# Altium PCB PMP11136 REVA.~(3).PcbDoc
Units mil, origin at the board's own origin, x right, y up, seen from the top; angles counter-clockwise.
Board outline 4950 x 3450 mil, 2 copper layers (Top Layer, Bottom Layer), stack 62 mil thick; 162 components, 94 nets, 407 pads, 20 vias.
Unrouted connection lines stored in the file: 297.
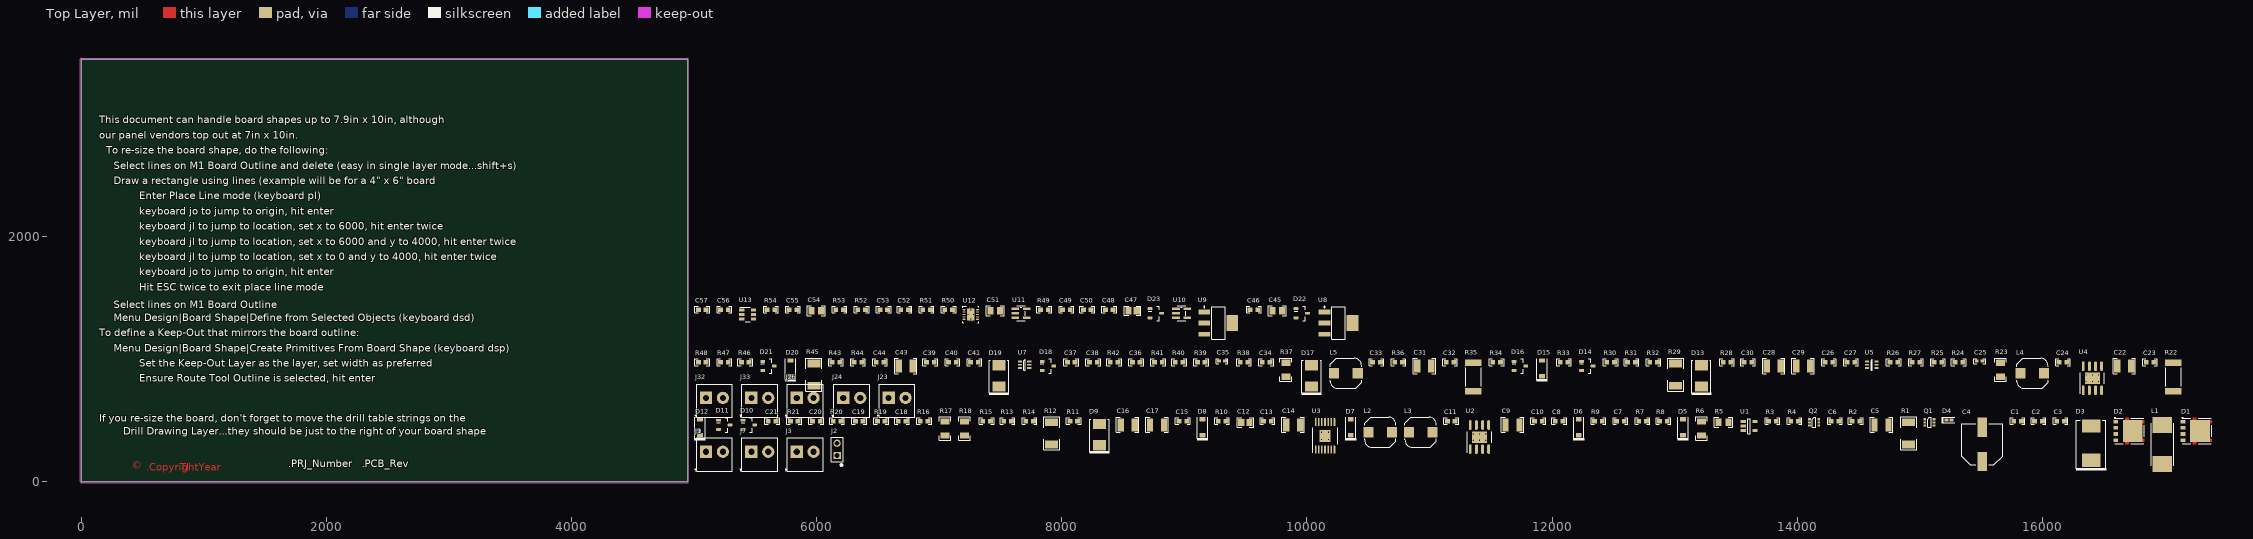
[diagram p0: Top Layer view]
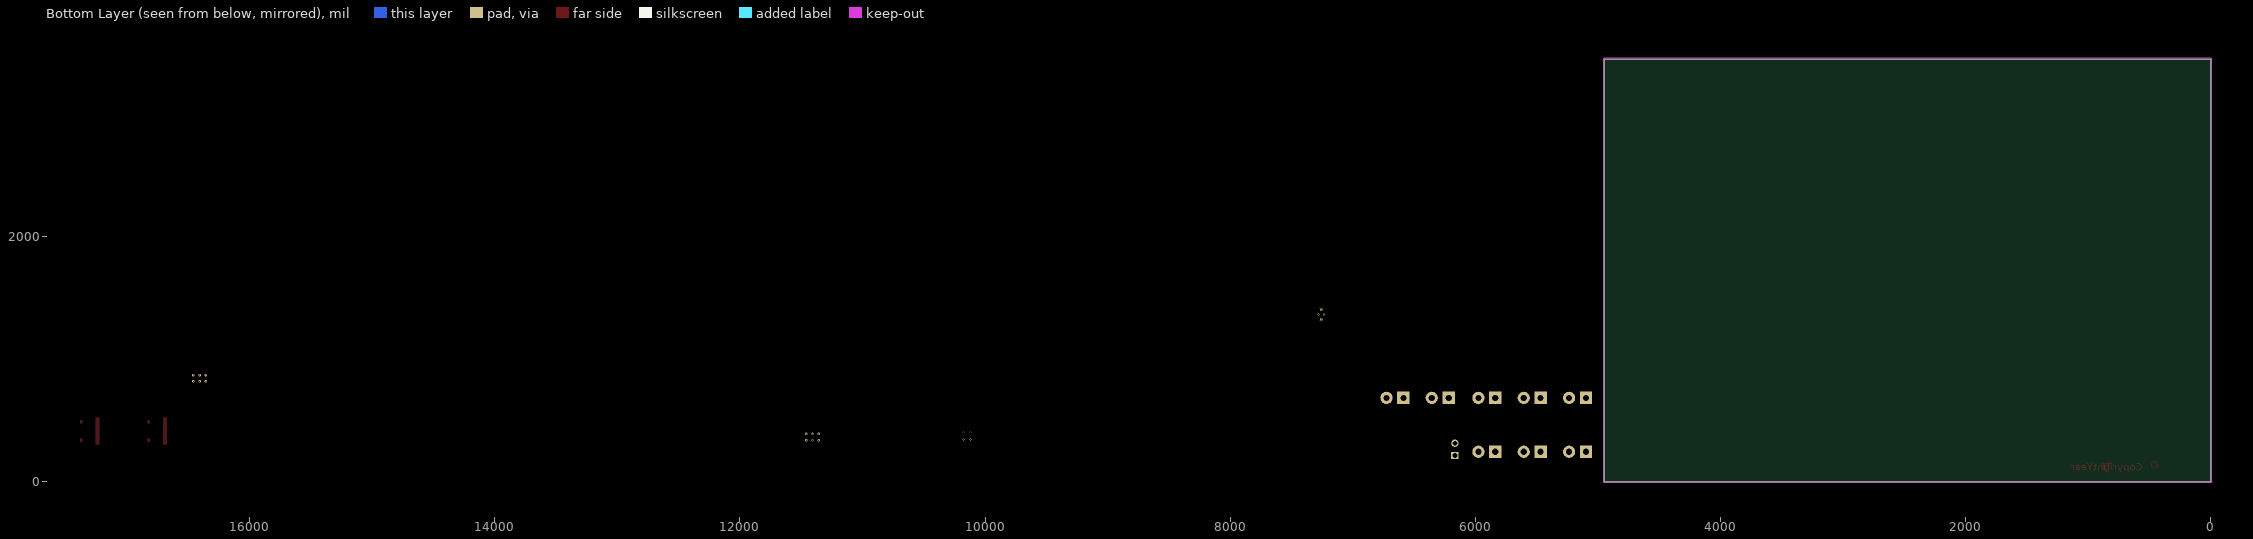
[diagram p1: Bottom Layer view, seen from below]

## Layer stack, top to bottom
Top Solder: solder mask 0.4, Solder Resist, Dk 3.5
Top Layer: signal copper 1.4
Dielectric1: core 59.2, FR-4, Dk 4.8
Bottom Layer: signal copper 1.4
Bottom Solder: solder mask 0.4, Solder Resist, Dk 3.5

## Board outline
0,0 4950,0 4950,3450 0,3450

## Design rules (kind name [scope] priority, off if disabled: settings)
AcuteAngle [All] p1: minimum=4.50000000000000E+0001 checktracksonly=FALSE
AssemblyTestPointUsage [All] p1: valid=2
Clearance Clearance_Keepouts [((IsTrack Or IsArc) And Not InPoly) And IsFree and IsKeepOut vs ((IsTrack Or IsArc) And Not InPoly) And IsFree and IsKeepOut] p1: gap=0
Clearance Clearance_BoardEdge_MountingHoles [OnCopper and InComponentClass('Mounting Holes') vs IsKeepOut] p2: gap=40
Clearance Clearance_BoardEdge_Poly [OnCopper and InPoly vs IsKeepOut] p3: gap=25
Clearance Clearance_BoardEdge [OnCopper and Not InComponentClass('Logo') and not InComponentClass('FiducialMark') and not InRegion(1000,500,4000,800) and Not IsKeepout vs IsKeepOut] p4: gap=75
Clearance Clearance_Poly [InPolygon] p5: gap=25
Clearance [All] p6: gap=7.87
ComponentClearance ComponentClearance_MountingHoles_FiducialMarks [InComponentClass('Mounting Holes') vs InComponentClass('FiducialMark')] p1: gap=50 collisioncheckmode=3 verticalgap=10 showdistances=FALSE
ComponentClearance ComponentClearance_Shunt [InComponentClass('Header') vs InComponentClass('Shunt')] p2: gap=0 collisioncheckmode=3 verticalgap=0 showdistances=FALSE
ComponentClearance ComponentClearance_Logo [InComponentClass('Logo')] p3: gap=50 collisioncheckmode=3 verticalgap=10 showdistances=FALSE
ComponentClearance ComponentClearance_ScrewToNut [(HasFootprint('NY PMS 440 0025 PH')) vs (HasFootprint('Keystone_1902C'))] p4: gap=5 collisioncheckmode=3 verticalgap=10 showdistances=FALSE
ComponentClearance ComponentClearance_MountingHoles [InComponentClass('Mounting Holes')] p5: gap=250 collisioncheckmode=3 verticalgap=100000 showdistances=FALSE
ComponentClearance ComponentClearance_SmallPassives [HasFootprint('0201*') or HasFootprint('0402*') or HasFootprint('0508') or HasFootprint('0603*') or HasFootprint('0612') or HasFootprint('0805*') or HasFootprint('0815*') or HasFootprint('0830*') or HasFootprint('1206*') or HasFootprint('1210*') or HasFootprint('1808*') or HasFootprint('1812*') or HasFootprint('1825*') or HasFootprint('2010*') or HasFootprint('2220*') or HasFootprint('2225*') or HasFootprint('2512*') or HasFootprint('2728*') or HasFootprint('3518*') vs HasFootprint('0201*') or HasFootprint('0402*') or HasFootprint('0508') or HasFootprint('0603*') or HasFootprint('0612') or HasFootprint('0805*') or HasFootprint('0815*') or HasFootprint('0830*') or HasFootprint('1206*') or HasFootprint('1210*') or HasFootprint('1808*') or HasFootprint('1812*') or HasFootprint('1825*') or HasFootprint('2010*') or HasFootprint('2220*') or HasFootprint('2225*') or HasFootprint('2512*') or HasFootprint('2728*') or HasFootprint('3518*')] p6: gap=20 collisioncheckmode=3 verticalgap=10 showdistances=FALSE
ComponentClearance ComponentClearance_THtoSMT [IsThruComponent vs IsSMTComponent] p7: gap=100 collisioncheckmode=3 verticalgap=30 showdistances=FALSE
ComponentClearance ComponentClearance_THtoTH [IsThruComponent vs IsThruComponent] p8: gap=118.11 collisioncheckmode=3 verticalgap=30 showdistances=FALSE
ComponentClearance [All] p9: gap=40 collisioncheckmode=3 verticalgap=10 showdistances=FALSE
DiffPairsRouting [All] p1: maxlimit=100 minlimit=10 mostfreqgap=10 toplayer_minwidth=15 toplayer_maxwidth=15 toplayer_prefwidth=15 bottomlayer_minwidth=15 bottomlayer_maxwidth=15 bottomlayer_prefwidth=15 maxuncoupledlength=1000
FabricationTestPointUsage TestPointUsage [All] p1: valid=2 allowmultiple=FALSE
FabricationTestpoint Testpoint [All] p1: side=3 testpointundercomponent=TRUE minsize=40 maxsize=100 preferedsize=60 minholesize=0 maxholesize=40 preferedholesize=32 testpointgrid=1 allowsidetop=TRUE allowsidebottom=TRUE usegrid=TRUE gridtolerance=0.01
FanoutControl Fanout_LCC [IsLCC] p1: bgadir=Out bgaviamode=Centered fanoutstyle=Auto fanoutdirection=Alternating viagrid=1 // Fanout_LCC (Default Rule)
FanoutControl Fanout_BGA [IsBGA] p2: bgadir=Out bgaviamode=Centered fanoutstyle=Auto fanoutdirection=Alternating viagrid=1 // Fanout_BGA (Default Rule)
FanoutControl Fanout_Default [All] p4: bgadir=Out bgaviamode=Centered fanoutstyle=Auto fanoutdirection=Alternating viagrid=1 // Fanout_Default (Default Rule)
FanoutControl Fanout_Small [(CompPinCount < 5)] p5: bgadir=Out bgaviamode=Centered fanoutstyle=Auto fanoutdirection=OutThenIn viagrid=1 // Fanout_Small (Default Rule)
HoleSize [All] p1: absolutevalues=TRUE maxlimit=251 minlimit=8 maxpercent=80.000 minpercent=20.000
MinimumAnnularRing MinimumAnnularRing_ThermalPadVias [IsVia and InAnyComponent] p1: minimumring=5.91
MinimumAnnularRing [All] p2: minimumring=9
MinimumSolderMaskSliver MinimumSolderMaskSliver_Logo [InComponentClass('Logo') vs InComponentClass('Logo')] p1: minsoldermaskwidth=0.7
MinimumSolderMaskSliver [All] p2: minsoldermaskwidth=3.94
PlaneConnect [All] p1: planeconnectstyle=Relief reliefexpansion=10 reliefentries=4 reliefconductorwidth=10 reliefairgap=10
PolygonConnect [All] p1: connectstyle=Relief reliefconductorwidth=10 reliefentries=4 polygonreliefangle="90 Angle" airgapwidth=10
RoutingVias ThermalPadVias [IsVia and InAnyComponent] p1: holewidth=7.87 width=19.68 viastyle="Through Hole" minholewidth=7.87 minwidth=19.68 maxholewidth=12.99 maxwidth=23.62
RoutingVias [All] p2: holewidth=16 width=34 viastyle="Through Hole" minholewidth=7.87 minwidth=26 maxholewidth=40 maxwidth=65
SilkToBoardRegionClearance [Not ((IsComment or IsDesignator) And (Hide <> 'False')) and not InRegion(1000,500,4000,800)] p1:
SilkToSilkClearance SilkToSilkClearance_Pb-FreeLogo [(HasFootprint('Pb-Free_Overlay_Medium') OR HasFootprint('Pb-Free_Overlay_Small')) vs (HasFootprint('Pb-Free_Overlay_Medium') OR HasFootprint('Pb-Free_Overlay_Small'))] p1: silktosilkclearance=0
SilkToSilkClearance [All] p2: silktosilkclearance=5
SilkToSolderMaskClearance "Silk to Solder Mask Opening" [All] p1: minsilkscreentomaskgap=1 clearancetoexposedcopper=FALSE
SolderMaskExpansion [All] p1: expansion=1.97
UnpouredPolygon [All] p1: allowunpoured=FALSE
Width [All] p1: maxlimit=100 minlimit=6 preferedwidth=10 checkconnectedcopper=TRUE
14 further rules are at their usual default settings.

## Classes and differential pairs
component class "PMP11136 REVA SHEET3": C45 C46 C47 C48 C49 C50 C51 C52 C53 C54 C55 C56 C57 D22 D23 J22 J23 J24 J25 J26 J27 J28 J29 J30 J31 J32 J33 J34 J35 J36 R49 R50 R51 R52 R53 R54 TP30 TP31 TP32 TP33 TP34 TP35 TP36 TP37 TP38 TP39 TP40 U8 U9 U10 U11 U12 U13
component class "PMP11136 REVA SHEET2": C22 C23 C24 C25 C26 C27 C28 C29 C30 C31 C32 C33 C34 C35 C36 C37 C38 C39 C40 C41 C42 C43 C44 D13 D14 D15 D16 D17 D18 D19 D20 D21 J11 J12 J13 J14 J15 J16 J17 J18 J19 J20 J21 L4 L5 R22 R23 R24 R25 R26 R27 R28 R29 R30 R31 R32 R33 R34 R35 R36 R37 R38 R39 R40 R41 R42 R43 R44 R45 R46 R47 R48 TP17 TP18 TP19 TP20 TP21 TP22 TP23 TP24 TP25 TP26 TP27 TP28 TP29 U4 U5 U6 U7
component class "PMP11136 REVA SHEET1": C1 C2 C3 C4 C5 C6 C7 C8 C9 C10 C11 C12 C13 C14 C15 C16 C17 C18 C19 C20 C21 D1 D2 D3 D4 D5 D6 D7 D8 D9 D10 D11 D12 J1 J2 J3 J4 J5 J6 J7 J8 J9 J10 L1 L2 L3 Q1 Q2 R1 R2 R3 R4 R5 R6 R7 R8 R9 R10 R11 R12 R13 R14 R15 R16 R17 R18 R19 R20 R21 TP1 TP2 TP3 TP4 TP5 TP6 TP7 TP8 TP9 TP10 TP11 TP12 TP13 TP14 TP15 TP16 U1 U2 U3
component class Header: J2 J4 J5 J6 J8 J10 J11 J12 J13 J16 J17 J18 J19 J22 J25 J27 J28 J29 J30 J31 J34 J35 J36

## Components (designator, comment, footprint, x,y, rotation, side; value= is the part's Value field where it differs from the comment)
C1 "C1608C0G2A102J" 0603 15798,496 r0 top
C2 "C1608X7R2A103K" 0603 15968,496 r0 top
C3 "C1608X7R1H224K080AB" 0603 16148,496 r0 top
C4 "EEE-FK1H101P" SM_RADIAL_F 15508,306 r90 top
C5 "C3225X7R1H475M250AB" 1210 14688,466 r0 top
C6 "C1608X7R1E105K" 0603 14308,496 r0 top
C7 "C1608X7R1H104K" 0603 12558,496 r0 top
C8 "C1608X7R1H103K" 0603 12058,496 r0 top
C9 "C3225X7R1H475M250AB" 1210 11678,466 r0 top
C10 "C1608X7R1H104K" 0603 11888,496 r0 top
C11 "C1608X7R1H104K" 0603 11178,496 r0 top
C12 "GRM21BR71A106KE51L" 0805 9498,486 r0 top
C13 "C1608X7R1E105K" 0603 9678,496 r0 top
C14 "C3225X7R1C226M250AC" 1210 9888,466 r0 top
C15 "" 0603 8988,496 r0 top
C16 "C3225X7R1C226M250AC" 1210 8538,466 r0 top
C17 "" 1210 8778,466 r0 top
C18 "C1608X7R1H473K" 0603 6698,496 r0 top
C19 "C1608C0G1H151J" 0603 6348,496 r0 top
C20 "" 0603 5998,496 r0 top
C21 "C1608C0G1E682J" 0603 5638,496 r0 top
C22 "C3225X7R1H475M250AB" 1210 16668,946 r0 top
C23 "C1608X7R1H104K" 0603 16878,976 r0 top
C24 "C1608X7R1H104K" 0603 16168,976 r0 top
C25 "C1005X7R1H104K050BB" 0402 15488,986 r0 top
C26 "C1608C0G1H100D" 0603 14258,976 r0 top
C27 "" 0603 14438,976 r0 top
C28 "C3225X7R1C226M250AC" 1210 13808,946 r0 top
C29 "" 1210 14048,946 r0 top
C30 "C1608C0G1H151J" 0603 13598,976 r0 top
C31 "C3225X7R1H475M250AB" 1210 10958,946 r0 top
C32 "C1608X7R1H104K" 0603 11168,976 r0 top
C33 "C1608X7R1H104K" 0603 10568,976 r0 top
C34 "C1608C0G1H151J" 0603 9668,976 r0 top
C35 "C1005X7R1H104K050BB" 0402 9308,986 r0 top
C36 "C1608X7R1H223K" 0603 8608,976 r0 top
C37 "C1608C0G1H152J" 0603 8078,976 r0 top
C38 "" 0603 8258,976 r0 top
C39 "" 0603 6928,976 r0 top
C40 "C1608C0G1H100D" 0603 7108,976 r0 top
C41 "C1608X7R1H104K" 0603 7288,976 r0 top
C43 "C3225X7R1C226M250AC" 1210 6728,946 r0 top
C44 "C1608C0G1H100D" 0603 6518,976 r0 top
C45 "GRM21BR71A106KE51L" 0805_HV 9758,1396 r0 top
C46 "C1608X7R1H104K" 0603 9568,1406 r0 top
C47 "GRM21BR71A106KE51L" 0805 8578,1396 r0 top
C48 "C1608X7R1H104K" 0603 8388,1406 r0 top
C49 "C1608X7R1E105K" 0603 8038,1406 r0 top
C50 "C1608X7R1E105K" 0603 8208,1406 r0 top
C51 "GRM21BR71A106KE51L" 0805_HV 7458,1396 r0 top
C52 "C1608X7R1E105K" 0603 6718,1406 r0 top
C53 "C1608X7R1E105K" 0603 6548,1406 r0 top
C54 "GRM21BR71A106KE51L" 0805_HV 5998,1396 r0 top
C55 "" 0603 5808,1406 r0 top
C56 "C1608X7R1H104K" 0603 5248,1406 r0 top
C57 "C1608C0G2A102J" 0603 5068,1406 r0 top
D1 "MBR1045MFST1G" SO-8FL 17258,416 r0 top
D2 "MBR1045MFST1G" SO-8FL 16708,416 r0 top
D3 "1.5SMC33AT3G" SMC 16398,316 r90 top
D4 "1PS79SB30" SOD-523 15238,506 r0 top
D5 "MMSZ4684T1G" SOD-123 13068,446 r90 top
D6 "MMSZ4705T1G" SOD-123 12218,446 r90 top
D7 "RB070M-30" SOD-123 10358,446 r90 top
D8 "MMSZ4699T1G" SOD-123 9148,446 r90 top
D9 "MBRS360BT3G" SMB 8308,386 r90 top
D10 "BAS16-7-F" SOT-23 5448,466 r0 top
D11 "BAS16-7-F" SOT-23 5248,466 r0 top
D12 "MMSZ5221B-7-F" SOD-123 5048,446 r90 top
D13 "MBRS360BT3G" SMB 13218,866 r90 top
D14 "BAS16-7-F" SOT-23 12288,946 r0 top
D15 "MMSZ5221B-7-F" SOD-123 11918,926 r90 top
D16 "BAS16-7-F" SOT-23 11738,946 r0 top
D17 "MBRS260T3G" SMB 10038,866 r90 top
D18 "BAS16-7-F" SOT-23 7888,946 r0 top
D19 "MBRS260T3G" SMB 7488,866 r90 top
D20 "MMSZ5221B-7-F" SOD-123 5788,926 r90 top
D21 "BAS16-7-F" SOT-23 5608,946 r0 top
D22 "BAS16-7-F" SOT-23 9958,1376 r0 top
D23 "BAS16-7-F" SOT-23 8768,1376 r0 top
J1 "ED555/2DS" TERM_BLK_ED555-2DS 5098,246 r0 top
J2 "PEC02SAAN" CONN_PEC02SAAN 6168,266 r90 top
J3 "ED555/2DS" TERM_BLK_ED555-2DS 5838,246 r0 top
J7 "ED555/2DS" TERM_BLK_ED555-2DS 5468,246 r0 top
J9 "ED555/2DS" TERM_BLK_ED555-2DS 5098,246 r0 top
J23 "ED555/2DS" TERM_BLK_ED555-2DS 6588,686 r0 top
J24 "ED555/2DS" TERM_BLK_ED555-2DS 6218,686 r0 top
J26 "ED555/2DS" TERM_BLK_ED555-2DS 5838,686 r0 top
J32 "ED555/2DS" TERM_BLK_ED555-2DS 5098,686 r0 top
J33 "ED555/2DS" TERM_BLK_ED555-2DS 5468,686 r0 top
L1 "28F0181-1SR-10" 28F0181 16978,306 r90 top
L2 "CLF6045NIT-2R2N-D" CLF6045NI-D 10598,406 r0 top
L3 "CLF6045NIT-4R7N-D" CLF6045NI-D 10928,406 r0 top
L4 "CLF6045NIT-2R2N-D" CLF6045NI-D 15918,886 r0 top
L5 "CLF6045NIT-4R7N-D" CLF6045NI-D 10318,886 r0 top
Q1 "BCR22PN" SOT-363 15078,486 r0 top
Q2 "BC847PN" SOT-363 14138,486 r0 top
R1 "CRCW20107R50JNEF" 2010 14908,396 r90 top
R2 "CRCW060320K0FKEA" 0603 14478,496 r0 top
R3 "CRCW060310K0FKEA" 0603 13798,496 r0 top
R4 "CRCW060310K0FKEA" 0603 13978,496 r0 top
R5 "CRCW080510K0FKEA" 0805_HV 13398,486 r0 top
R6 "CRCW12062K00FKEA" 1206 13218,436 r90 top
R7 "CRCW06032K87FKEA" 0603 12738,496 r0 top
R8 "CRCW06033K01FKEA" 0603 12908,496 r0 top
R9 "CRCW0603100KFKEA" 0603 12378,496 r0 top
R10 "CRCW060334K0FKEA" 0603 9308,496 r0 top
R11 "CRCW0603110RFKEA" 0603 8098,496 r0 top
R12 "" 2010 7918,396 r90 top
R13 "CRCW060310K0FKEA" 0603 7558,496 r0 top
R14 "CRCW060310K0FKEA" 0603 7738,496 r0 top
R15 "" 0603 7388,496 r0 top
R16 "CRCW060353K6FKEA" 0603 6878,496 r0 top
R17 "CRCW120615R0FKEA" 1206 7048,436 r90 top
R18 "CRCW120615R0FKEA" 1206 7208,436 r90 top
R19 "CRCW060310K0FKEA" 0603 6528,496 r0 top
R20 "CRCW06030000Z0EA" 0603 6168,496 r0 top
R21 "CRCW0603200RFKEA" 0603 5818,496 r0 top
R22 "CSRN2512FKR200" 2512 17068,856 r90 top
R23 "CSR1206FK10L0" 1206 15658,916 r90 top
R24 "CRCW06034K02FKEA" 0603 15318,976 r0 top
R25 "CRCW06034K99FKEA" 0603 15148,976 r0 top
R26 "" 0603 14788,976 r0 top
R27 "CRCW060363K4FKEA" 0603 14968,976 r0 top
R28 "CRCW06030000Z0EA" 0603 13428,976 r0 top
R29 "" 2010 13008,876 r90 top
R30 "CRCW0603200RFKEA" 0603 12478,976 r0 top
R31 "CRCW060310K0FKEA" 0603 12648,976 r0 top
R32 "CRCW06034K99FKEA" 0603 12828,976 r0 top
R33 "CRCW0603124KFKEA" 0603 12098,976 r0 top
R34 "CRCW060310K0FKEA" 0603 11548,976 r0 top
R35 "CSRN2512FKR200" 2512 11358,856 r90 top
R36 "CRCW060310K0FKEA" 0603 10748,976 r0 top
R37 "CSR1206FK10L0" 1206 9828,916 r90 top
R38 "CRCW06030000Z0EA" 0603 9488,976 r0 top
R39 "CRCW06034K02FKEA" 0603 9138,976 r0 top
R40 "CRCW060363K4FKEA" 0603 8958,976 r0 top
R41 "CRCW06034K99FKEA" 0603 8788,976 r0 top
R42 "CRCW060354K9FKEA" 0603 8428,976 r0 top
R43 "CRCW0603100KFKEA" 0603 6158,976 r0 top
R44 "CRCW060310K0FKEA" 0603 6338,976 r0 top
R45 "" 2010 5978,876 r90 top
R46 "CRCW06034K99FKEA" 0603 5418,976 r0 top
R47 "CRCW0603200RFKEA" 0603 5248,976 r0 top
R48 "CRCW0603124KFKEA" 0603 5068,976 r0 top
R49 "CRCW060310K0FKEA" 0603 7858,1406 r0 top
R50 "CRCW060310K0FKEA" 0603 7078,1406 r0 top
R51 "CRCW06032K49FKEA" 0603 6898,1406 r0 top
R52 "CRCW06034K99FKEA" 0603 6368,1406 r0 top
R53 "CRCW060310K0FKEA" 0603 6188,1406 r0 top
R54 "CRCW060349K9FKEA" 0603 5628,1406 r0 top
U1 "TPS7B4250QDBV" DBV0005A_N 13608,456 r0 top
U2 "LMR14030PQDDAQ1" DDA0008E_N 11408,366 r90 top
U3 "TPS61175PWP" PWP0014E_N 10148,376 r90 top
U4 "LMR14030PQDDAQ1" DDA0008E_N 16408,846 r90 top
U5 "INA213AQDCKRQ1" DCK0006A_N 14608,956 r0 top
U7 "INA213AQDCKRQ1" DCK0006A_N 7698,956 r0 top
U8 "TPS7B6933QDCYRQ1" DCY0004A_N 10258,1296 r0 top
U9 "TPS7B6950QDCYRQ1" DCY0004A_N 9278,1296 r0 top
U10 "TLV70033QDDCRQ1" DDC0005A_N 8978,1376 r0 top
U11 "TLV70018QDDCRQ1" DDC0005A_N 7668,1376 r0 top
U12 "TPS74701QDRCRQ1" DRC0010A 7258,1366 r0 top
U13 "TPS3808G12QDBVRQ1" DBV0006A_N 5438,1366 r0 top

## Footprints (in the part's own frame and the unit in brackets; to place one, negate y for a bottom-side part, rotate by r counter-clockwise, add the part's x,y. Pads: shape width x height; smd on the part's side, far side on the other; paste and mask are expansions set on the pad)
28F0181 [mm] "SMD, 2-Leads, Body 8.74x4.65mm"
  rect 3.3x4.06 smd: 1(-4.015,0) 2(4.015,0)
  silkscreen extent -4.37,-2.32 4.37,2.32, body extent -4.76,-2.32 4.77,2.32, height 3.05
0402 [mm] "0402 from SM-752 data"
  rect 0.8x0.6 smd: 1(-0.6,0) 2(0.6,0)
  silkscreen extent -1.22,-0.52 1.22,0.52, body extent -0.55,-0.3 0.55,0.3, height 0.6
0603 [mm] "0603 from SM-752 data"
  rect 1x0.95 smd: 1(-0.8,0) 2(0.8,0)
  silkscreen extent -1.52,-0.69 1.52,0.69, body extent -0.87,-0.47 0.87,0.47, height 0.85
0805 [mm] "0805 from SM-752 data"
  rect 1.3x1.5 smd: 1(-0.85,0) 2(0.85,0)
  silkscreen extent -1.72,-0.97 1.72,0.97, body extent -1.1,-0.72 1.1,0.72, height 1.1
0805_HV [mil] "0805 with 30mil clearance between pads"
  rect 50x63 smd: 1(-40,0) 2(40,0)
  silkscreen extent -74,-40 74,40, body extent -43,-29 43,29, height 43
1206 [mm] "1206 from SM-752 data"
  rect 1.3x1.85 smd: 1(-1.45,0) 2(1.45,0)
  silkscreen extent -2.4,-1.21 2.4,1.21, body extent -1.7,-0.9 1.7,0.9, height 1.35
1210 [mm] "1210 from SM-752 data"
  rect 1.3x2.7 smd: 1(-1.45,0) 2(1.45,0)
  silkscreen extent -2.32,-1.57 2.32,1.57, body extent -1.7,-1.35 1.7,1.35, height 1.35
2010 [mm] "Chip Capacitor, Body 5.08x2.54mm, IPC Medium Density"
  rect 1.6x2.7 smd: 1(-2.3,0) 2(2.3,0)
  silkscreen extent -3.42,-1.65 3.42,1.65, body extent -2.73,-1.45 2.73,1.45, height 1.66
2512 [mm] "Chip Resistor, Body 6.3x3.2mm, IPC Medium Density"
  rect 1.3x3.4 smd: 1(-2.95,0) 2(2.95,0)
  silkscreen extent -1.9,-1.6 1.9,1.6, body extent -3.22,-1.67 3.22,1.67, height 0.71
CLF6045NI-D [mm] "SMD, 2-Leads, Body 6.3x6mm, Pitch 4.9mm"
  rect 2.1x2.2 smd: 1(-2.45,0) 2(2.45,0)
  silkscreen extent -3.25,-3.1 3.25,3.1, body extent -3.26,-3.11 3.26,3.11, height 4.8
CONN_PEC02SAAN [mm] "SULLINS"
  rect 1.5x1.5 hole 1.016: 1(-1.27,0)
  round 1.5 hole 1.016: 2(1.27,0)
  silkscreen extent -3.45,-1.27 2.54,1.27, body extent -2.54,-1.27 2.54,1.27, height 8.38
DBV0005A_N [mm] "SOT23, 5-Leads, Body 2.9x1.6mm, Pitch 0.95mm, Lead Span 2.8mm, IPC Medium Density"
  rect 1.1x0.65 smd: 1(-1.2,0.95) 2(-1.2,0) 3(-1.2,-0.95) 4(1.2,-0.95) 5(1.2,0.95)
  silkscreen extent -0.25,-1.55 0.25,1.55, body extent -1.42,-1.46 1.42,1.46, height 1.08
DBV0006A_N [mm] "SOT23, 6-Leads, Body 2.9x1.6mm, Pitch 0.95mm, Lead Span 2.8mm, IPC Medium Density"
  rect 1.1x0.65 smd: 1(-1.2,0.95) 2(-1.2,0) 3(-1.2,-0.95) 4(1.2,-0.95) 5(1.2,0) 6(1.2,0.95)
  silkscreen extent -1.68,-1.55 0.5,1.55, body extent -1.42,-1.46 1.42,1.46, height 1.11
DCK0006A_N [mm] "SOT23, 6-Leads, Body 2x1.3mm, Pitch 0.65mm, Lead Span 2.1mm, IPC Medium Density"
  rect 0.85x0.4 smd: 1(-0.95,0.65) 2(-0.95,0) 3(-0.95,-0.65) 4(0.95,-0.65) 5(0.95,0) 6(0.95,0.65)
  silkscreen extent -0.15,-1.1 0.15,1.1, body extent -1.14,-1 1.14,1, height 0.94
DCY0004A_N [mm] "SOT223/SC73, 4-Leads, Body 6.5x3.5mm, Pitch 2.3mm, Lead Span 7mm, IPC Medium Density"
  rect 2.4x1 smd: 1(-2.9,2.3) 2(-2.9,0) 3(-2.9,-2.3)
  rect 2.4x3.3 smd: 4(2.9,0)
  silkscreen extent -3.02,-3.35 1.4,3.47, body extent -3.5,-3.25 3.5,3.25, height 1.62
DDA0008E_N [mm]
  oval 2x0.6 smd: 1(-2.5,1.905) 2(-2.5,0.635) 3(-2.5,-0.635) 4(-2.5,-1.905) 5(2.5,-1.905) 6(2.5,-0.635) 7(2.5,0.635) 8(2.5,1.905)
  rect 2.4x3.1 smd: 9(0,0)
  silkscreen extent -3.22,-2.5 1.15,2.5, body extent -2.98,-2.45 2.98,2.45, height 1.5
DDC0005A_N [mil]
  rect 62x22 smd: 1(-46,37.4) 2(-46,0) 3(-46,-37.4) 4(46,-37.4) 5(46,37.4)
  silkscreen extent -34,-60 34,60, body extent -60,-60 60,60, height 43
DRC0010A [mm] "SON, 10-Leads, Body 3x3mm, Pitch 0.5mm, Thermal Pad 2.4x1.65mm, TI Recommended"
  oval 0.6x0.24 smd: 1(-1.4,1) 2(-1.4,0.5) 3(-1.4,0) 4(-1.4,-0.5) 5(-1.4,-1) 6(1.4,-1) 7(1.4,-0.5) 8(1.4,0) 9(1.4,0.5) 10(1.4,1)
  rect 1.65x2.4 smd paste-0.825: 11(0,0)
  Top Layer region: 0.135,-1.5 0.365,-1.5 0.365,-1.1 0.135,-1.1
  Top Layer region: -0.135,-1.1 -0.365,-1.1 -0.365,-1.5 -0.135,-1.5
  Top Layer region: -0.135,1.5 -0.365,1.5 -0.365,1.1 -0.135,1.1
  Top Layer region: 0.135,1.1 0.365,1.1 0.365,1.5 0.135,1.5
  silkscreen extent -1.7,-1.7 1.7,1.7, body extent -1.55,-1.55 1.55,1.55, height 1.01
PWP0014E_N [mm] "TSOP, 14-Leads, Body 5x4.4mm, Pitch 0.65mm, Thermal Pad 3x3 mm, IPC Medium Density"
  oval 1.7x0.35 smd: 1(-2.85,1.95) 2(-2.85,1.3) 3(-2.85,0.65) 4(-2.85,0) 5(-2.85,-0.65) 6(-2.85,-1.3) 7(-2.85,-1.95) 8(2.85,-1.95) 9(2.85,-1.3) 10(2.85,-0.65) 11(2.85,0) 12(2.85,0.65) 13(2.85,1.3) 14(2.85,1.95)
  rect 2.46x2.31 smd: 15(0,0)
  silkscreen extent -3.5,-2.65 1.7,2.65, body extent -3.21,-2.5 3.21,2.5, height 0.99
SM_RADIAL_F [mm] "8 x 10.2mm:  Panasonic F"
  rect 4x2 smd: 1(-3.55,0) 2(3.55,0)
  silkscreen extent -4.25,-4.25 4.25,4.25, body extent -4.26,-4.26 4.26,4.26, height 10.5
SMB [mil] "Molded Diode, 2-Leads, Body 5.4x3.6mm, IPC Medium Density, based on OnSemi component dimensions"
  rect 85x107.99 smd: 1(-87.01,0) 2(87.01,0)
  silkscreen extent -155,-82 125,82, body extent -106,-71 106,71, height 91
SMC [mil] "Molded Diode, 2-Leads, Body 6.9x5.8mm, IPC Medium Density, based on OnSemi component dimensions and land patterns"
  rect 110x150 smd: 1(-140.49,0) 2(140.49,0)
  silkscreen extent -221,-124 189,123, body extent -156,-116 156,116, height 91
SO-8FL [mm] "ON SEMICONDUCTOR, DFN5 5x6, 1.27P, CASE 488AA"
  rect 1x0.75 smd: 1(-2.795,1.905) 2(-2.795,0.635) 3(-2.795,-0.635) 4(-2.795,-1.905)
  rect 4.055x4.56 smd: 5(0.698,0)
  Top Layer region: 0,-2.775 0,2.775 -0.905,2.775 -0.905,-2.775
  Top Layer region: 3.2,1.53 3.2,2.28 2.655,2.28 2.655,1.53
  Top Layer region: 3.2,-2.28 3.2,-1.53 2.65,-1.53 2.65,-2.28
  silkscreen extent -3.1,-2.6 3.1,2.9, body extent -3.17,-2.67 3.17,2.67, height 1.11
SOD-123 [mm] "On Semi recommended land pattern"
  rect 0.915x1.22 smd: 1(-1.637,0) 2(1.637,0)
  silkscreen extent -2.74,-1.17 2.03,1.17, body extent -1.93,-0.9 1.93,0.9, height 1.35
SOD-523 [mm] "NXP Semiconductor recommended land pattern, nominal STEP model"
  rect 0.8x0.6 smd paste-0.05: 1(-0.55,0) 2(0.55,0)
  silkscreen extent -1.6,-0.64 1.2,0.64, body extent -0.8,-0.4 0.8,0.4, height 0.72
SOT-23 [mm] "SOT23, 3-Leads, Body 2.9x1.3mm, Pitch 0.95mm, Lead Span 2.5mm, IPC Medium Density"
  rrect50% 1x0.6 smd: 1(-1.2,0.95) 2(-1.2,-0.95) 3(1.2,0)
  silkscreen extent -1.63,-1.5 0.7,1.5, body extent -1.16,-1.45 1.21,1.45, height 1
SOT-363 [mm]
  rect 0.6x0.42 smd mask+0.051: 1(-0.95,0.65) 2(-0.95,0) 3(-0.95,-0.65) 4(0.95,-0.65) 5(0.95,0) 6(0.95,0.65)
  silkscreen extent -0.38,-1.02 0.38,1.02, body extent -1.1,-1.1 1.1,1.1, height 1.12
TERM_BLK_ED555-2DS [mil]
  rect 100x100 hole 50: 1(0,0)
  round 100 hole 50: 2(138,0)
  silkscreen extent -93,-161 215,113, body extent -69,-150 207,106, height 323

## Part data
C1 C57: "CAP, CERM, 1000 pF, 100 V, +/- 5%, C0G/NP0, 0603"
C2: "CAP, CERM, 0.01 µF, 100 V, +/- 10%, X7R, 0603"
C3: "CAP, CERM, 0.22 µF, 50 V, +/- 10%, X7R, 0603"
C4: "CAP, AL, 100 µF, 50 V, +/- 20%, 0.34 ohm, SMD"
C5 C9 C22 C31: library part C3225X7R1E106M, "CAP, CERM, 4.7uF, 50V, +/-20%, X7R, 1210"
C6 C13 C49 C50 C52 C53: library part C1608X7R1C105K, "CAP, CERM, 1uF, 25V, +/-10%, X7R, 0603"
C7 C10 C11 C23 C24 C32 C33 C41 C46 C48 C56: "CAP, CERM, 0.1uF, 50V, +/-10%, X7R, 0603"
C8: "CAP, CERM, 0.01 µF, 50 V, +/- 10%, X7R, 0603"
C12 C47: "CAP, CERM, 10uF, 10V, +/-10%, X7R, 0805"
C14 C16 C28 C43: library part C3225X7R1C226M, "CAP, CERM, 22 µF, 16 V, +/- 20%, X7R, 1210"
C15 C20 C27 C38 C39 C55: library part C1608C0G1H102J, "CAP, CERM, open, 0603"
C17 C29: library part C3225X7R1C226M, "CAP, open, 1210"
C18: "CAP, CERM, 0.047 µF, 50 V, +/- 10%, X7R, 0603"
C19 C30 C34: "CAP, CERM, 150 pF, 50 V, +/- 5%, C0G/NP0, 0603"
C21: "CAP, CERM, 6800 pF, 25 V, +/- 5%, C0G/NP0, 0603"
C25 C35: "CAP, CERM, 0.1uF, 50V, +/-10%, X7R, 0402"
C26 C40 C44: "CAP, CERM, 10 pF, 50 V, +/- 5%, C0G/NP0, 0603"
C36: "CAP, CERM, 0.022 µF, 50 V, +/- 10%, X7R, 0603"
C37: "CAP, CERM, 1500 pF, 50 V, +/- 5%, C0G/NP0, 0603"
C45 C51 C54: "CAP, CERM, 10 µF, 10 V, +/- 10%, X7R, 0805"
D1 D2: "Diode, Schottky, 45 V, 10 A, 6.15x1.00x5.15mm"
D3: library part 1.5SMC6.8A, "Diode, TVS, Uni, 33 V, 1500 W, SMC"
D4: library part 1PS79SB70,115, "Diode, Schottky, 30 V, 0.2 A, SOD-523"
D5: "Diode, Zener, 3.3 V, 500 mW, SOD-123"
D6: "Diode, Zener, 18 V, 500 mW, SOD-123"
D7: library part B130LAW-7-F, "Diode, Schottky, 30V, 1.5A, SOD-123"
D8: "Diode, Zener, 12 V, 500 mW, SOD-123"
D9 D13: library part MBRS260T3G, "Diode, Schottky, 60V, 3A, SMB"
D10 D11 D14 D16 D18 D21 D22 D23: "Diode, Ultrafast, 75V, 0.3A, SOT-23"
D12 D15 D20: "Diode, Zener, 2.4V, 500 mW, SOD-123"
D17 D19: "Diode, Schottky, 60V, 2A, SMB"
J1 J3 J7 J9 J23 J24 J26 J32 J33: "Terminal Block, 6A, 3.5mm Pitch, 2-Pos, TH"
J2: "Header, 100mil, 2x1, Tin, TH"
L1: "Ferrite Bead, 115 ohm @ 100MHz, 10A, SMD, 2-Leads, Body 8.74x4.65mm"
L2 L4: "Inductor, Wirewound, Ferrite, 2.2 µH, 4.1 A, 0.015 ohm, SMD"
L3 L5: "Inductor, Wirewound, Ferrite, 4.7 µH, 3.1 A, 0.023 ohm, SMD"
Q1: library part "BCR 48PN E6327, Infineon Technologies", "Transistor, NPN/PNP Pair, 50 V, 0.1 A, SOT-363"
Q2: library part "BC 846PN H6327, Infineon Technologies", "Transistor, NPN/PNP Pair, 45 V, 0.1 A, SOT-363"
R1: "RES, 7.5, 5%, 0.75 W, 2010"
R2: "RES, 20.0 k, 1%, 0.1 W, 0603"
R3 R4 R13 R14 R19 R31 R34 R36 R44 R49 R50 R53: "RES, 10.0 k, 1%, 0.1 W, 0603"
R5: "RES, 10.0 k, 1%, 0.125 W, 0805"
R6: "RES, 2.00 k, 1%, 0.25 W, 1206"
R7: "RES, 2.87 k, 1%, 0.1 W, 0603"
R8: "RES, 3.01 k, 1%, 0.1 W, 0603"
R9 R43: "RES, 100 k, 1%, 0.1 W, 0603"
R10: "RES, 34.0 k, 1%, 0.1 W, 0603"
R11: "RES, 110, 1%, 0.1 W, 0603"
R12 R29 R45: library part CRCW20102R70JNEF, "RES, open, 2010"
R15 R26: library part CRCW060312K1FKEA, "RES, 12.1 k, 0.1%, 0.1 W, 0603"
R16: "RES, 53.6 k, 1%, 0.1 W, 0603"
R17 R18: "RES, 15.0, 1%, 0.25 W, 1206"
R20 R28 R38: "RES, 0, 5%, 0.1 W, 0603"
R21 R30 R47: "RES, 200, 1%, 0.1 W, 0603"
R22 R35: "RES, 0.2, 1%, 2 W, 2512"
R23 R37: "RES, 0.01, 1%, 0.5 W, 1206"
R24 R39: "RES, 4.02 k, 1%, 0.1 W, 0603"
R25 R32 R41 R46 R52: "RES, 4.99 k, 1%, 0.1 W, 0603"
R27 R40: "RES, 63.4 k, 1%, 0.1 W, 0603"
R33 R48: "RES, 124 k, 1%, 0.1 W, 0603"
R42: "RES, 54.9 k, 1%, 0.1 W, 0603"
R51: "RES, 2.49 k, 1%, 0.1 W, 0603"
R54: "RES, 49.9 k, 1%, 0.1 W, 0603"
U1: "Low Dropout Voltage Tracking LDO, DBV0005A"
U2 U4: library part LMR14030PDDAR, "LMR14030PQDDAQ1, DDA0008E"
U3: "3-A High Voltage Boost Converter with Soft-start and Programmable Switching Frequency, PWP0014E"
U5 U7: library part INA213AIDCK, "Voltage Output, High or Low Side Measurement, Bi-Directional Zero-Drift Series Current-Shunt Monitor, DCK0006A"
U8 U9: "High Voltage Ultra Low Iq - Low Drop Out Regulator, DCY0004A"
U10: "Single Output Automotive LDO, 200 mA, Fixed 3.3 V Output, 2 to 5.5 V Input, with Low IQ, 5-pin SOT (DDC), -40 to 125 degC, Green (RoHS & no Sb/Br)"
U11: "Single Output Automotive LDO, 300 mA, Fixed 1.8 V Output, 2 to 5.5 V Input, with Low IQ, 5-pin SOT (DDC), -40 to 125 degC, Green (RoHS & no Sb/Br)"
U12: "Single Output Automotive LDO, 500 mA, Adjustable 0.8 to 3.6 V Output, 0.8 to 5.5 V Input, with Programmable Soft Start, 10-pin SON (DRC), -40 to 125 degC, Green (RoHS & no Sb/Br)"
U13: library part TPS3808G18QDBVRQ1, "LOW-QUIESCENT-CURRENT PROGRAMMABLE-DELAY SUPERVISORY CIRCUIT, DBV0006A"

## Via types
v1: diameter 19.68, hole 7.87, Top Layer to Bottom Layer, tented top, 12 vias
v2: diameter 19.68, hole 7.87, Top Layer to Bottom Layer, 4 vias
v3: diameter 15.75, hole 7.87, Top Layer to Bottom Layer, 4 vias

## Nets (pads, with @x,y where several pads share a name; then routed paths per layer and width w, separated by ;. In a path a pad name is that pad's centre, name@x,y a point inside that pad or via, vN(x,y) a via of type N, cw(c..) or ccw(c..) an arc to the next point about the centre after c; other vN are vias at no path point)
"3.3V PG": R13.2 U2.6
3.3V_SW: C16.1 C17.1 C56.1 J9.1 L2.2 R4.2 R10.2 R13.1 R34.1 R36.1 R54.2 U13.6
5V#1PG: R34.2 U4.6
GND: C1.2 C2.2 C3.2 C4.2 C5.1 C6.2 C7.2 C8.2 C9.1 C10.2 C12.2 C13.2 C14.2 C16.2 C17.2 C18.2 C20.2 C21.2 C22.1 C23.2 C25.2 C28.2 C29.2 C31.1 C32.2 C35.2 C36.2 C39.2 C41.2 C43.2 C44.2 C45.2 C46.2 C47.2 C48.2 C49.2 C50.2 C51.2 C52.2 C53.2 C54.2 C55.2 C56.2 C57.2 D3.2 D5.2 D9.2 D11.1 D12.2 D13.2 D15.2 D16.1 D19.2 D20.2 D21.1 J1.2 J3.2 J9.2 J23.2 J24.2 J26.2 J32.2 J33.2 Q1.1 Q2.1 R7.2 R8.1 R9.2 R12.1 R14.1 R15.1 R16.1 R17.1 R18.1 R21.1 R29.1 R30.1 R31.1 R32.2 R43.1 R44.1 R45.1 R46.2 R47.1 R52.1 U1.2 U1.5 U2.7 U2.9 U3.7 U3.11 U3.12 U3.13 U3.14 U3.15 U4.7 U4.9 U5.2 U7.2 U8.2 U8.4 U9.2 U9.4 U10.2 U11.2 U12.6 U12.11 U13.2
  other v1: 11356.82,340.41 11408,340.41 11459.18,340.41 11356.82,391.59 11408,391.59 11459.18,391.59 16356.82,820.41 16408,820.41 16459.18,820.41 16356.82,871.59 16408,871.59 16459.18,871.59
  other v2: 7258,1328.6 7235.36,1366 7280.64,1366 7258,1403.4
  other v3: 10118.47,346.47 10177.53,346.47 10118.47,405.53 10177.53,405.53
NetC1_1: C1.1 C2.1 J1.1 L1.1
NetC5_2: C5.2 J2.1 Q2.4 R1.1 R3.2 U1.4
NetC7_1: C7.1 Q2.6 R4.1
NetC8_1: C8.1 D6.1 R6.2 R9.1 U1.1
NetC9_2: C9.2 C10.1 U2.2
NetC11_1: C11.1 U2.1
NetC12_1: C12.1 C13.1 L3.1 U3.3
NetC14_1: C14.1 D7.1 D8.1 J7.1
NetC15_2: C15.2 R12.2
NetC18_1: C18.1 U3.5
NetC19_1: C19.1 D10.1 D11.3 R21.2 U3.6
NetC19_2: C19.2 R20.2
NetC20_1: C20.1 R19.2 U3.8
NetC21_1: C21.1 R19.1
NetC22_2: C22.2 C23.1 U4.2
NetC24_1: C24.1 U4.1
NetC24_2: C24.2 C27.1 D13.1 L4.1 U4.8
NetC25_1: C25.1 C28.1 C29.1 L4.2 R23.1 R25.1 R27.2 U5.3 U5.5
NetC26_1: C26.1 R24.2
NetC26_2: C26.2 C30.1 D14.1 D16.3 R26.1 R30.2
NetC27_2: C27.2 R29.2
NetC30_2: C30.2 R28.2
NetC31_2: C31.2 C32.1
NetC33_1: C33.1
NetC33_2: C33.2 C38.1 D19.1 L5.1
NetC34_1: C34.1 C40.2 D18.1 D21.3 R42.1 R47.2
NetC34_2: C34.2 R38.2
NetC35_1: C35.1 C41.1 D17.1 R37.1 R40.2 R41.1 U7.3 U7.5
NetC36_1: C36.1
NetC37_1: C37.1 C44.1
NetC37_2: C37.2 R43.2
NetC38_2: C38.2 R45.2
NetC39_1: C39.1
NetC40_1: C40.1 R39.2
NetC42_1: C43.1 D17.2 L5.2
NetC45_1: C45.1 J23.1 U8.3
NetC46_1: C46.1 D22.3 U8.1
NetC47_1: C47.1 C49.1 J24.1 U9.3 U10.1
NetC48_1: C48.1 D23.3 U9.1
NetC50_1: C50.1 J26.1 U10.5
NetC51_1: C51.1 R49.2 R50.2 U12.1 U12.2 U12.4
NetC52_1: C52.1 J33.1 U11.5
NetC53_1: C53.1 U11.1
NetC54_1: C54.1 C57.1 J32.1 R51.2 U12.9 U12.10 U13.5
NetC55_1: C55.1 U12.7
NetD1_1: D1.1 D1.2 D1.3 D2.1 D2.2 D2.3 L1.2
NetD4_1: D4.1 J3.1
NetD4_2: D4.2 J2.2 Q2.5 R1.2
NetD5_1: D5.1 R3.1 R7.1
NetD7_2: D7.2 L3.2 U3.1 U3.2
NetD8_2: D8.2 R11.2 U3.9
NetD10_3: D10.3 D12.1
NetD14_3: D14.3 D15.1
NetD18_3: D18.3 D20.1
NetD22_1: D22.1
NetD23_1: D23.1
NetJ5_1: U2.3
NetJ7_2: J7.2 R11.1 R17.2 R18.2
NetJ10_2: U3.4
NetJ12_1: R22.2
NetJ13_1: U4.3
NetJ14_1: R22.1 R23.2 U5.4
NetJ17_1: R36.2
NetJ19_1: R35.2
NetJ20_1: R35.1 R37.2 U7.4
NetJ27_2: U10.3
NetJ30_1: R49.1 U12.3
NetJ31_2: R53.2 U11.3
NetJ34_2: R50.1 U12.5
NetJ35_1: R53.1
NetJ36_1: R54.1 U13.1
NetQ1_2: Q1.2
NetQ1_3: Q1.3 R6.1
NetQ1_5: Q1.5 Q1.6 R2.1
NetQ2_2: Q2.2 R5.1 R8.2
NetQ2_3: Q2.3 R5.2
NetR10_1: R10.1 R14.2 U2.5
NetR15_2: R15.2 U2.4
NetR16_2: R16.2 U3.10
NetR24_1: R24.1 R26.2 U4.4
NetR25_2: R25.2 R32.1 U5.1
NetR27_1: R27.1 R31.2 R33.2 U4.5
NetR33_1: R33.1 U5.6
NetR39_1: R39.1 R42.2
NetR40_1: R40.1 R44.2 R48.2
NetR41_2: R41.2 R46.1 U7.1
NetR48_1: R48.1 U7.6
NetR51_1: R51.1 R52.2 U12.8
SYNC: C11.2 C15.1 D9.1 L2.1 R20.1 R28.1 R38.1 U2.8
VIN_FLTR: C3.1 C4.1 C6.1 D1.5 D2.5 D3.1 Q1.4 R2.2 U1.3
pads on no net: D1.4 D2.4 D6.2 D10.2 D11.2 D14.2 D16.2 D18.2 D21.2 D22.2 D23.2 U10.4 U11.4 U13.3 U13.4

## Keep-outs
Keep-Out Layer:
  lines w10: -5,0 ccw(c0,0) 0,-5 ; -5,0 ccw(c0,0) 0,-5 ; -5,0 -5,3450 ; -5,3450 cw(c0,3450) 0,3455 ; -5,3450 cw(c0,3450) 0,3455 ; 0,-5 4950,-5 ; 0,3455 4950,3455 ; 4950,-5 ccw(c4950,0) 4955,0 ; 4950,-5 ccw(c4950,0) 4955,0 ; 4950,3455 cw(c4950,3450) 4955,3450 ; 4950,3455 cw(c4950,3450) 4955,3450 ; 4955,0 4955,3450
  text ".Layer_Name" at 577,-858.49 h60

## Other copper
Top Layer:
  text ".CopyrightYear" at 532,90 h60
  text "TI" at 808,90 h60
  text "©" at 415,86.48 h105
  text ".Layer_Name" at 577,-858.49 h60
Bottom Layer:
  text ".Layer_Name" at 577,-858.49 h60

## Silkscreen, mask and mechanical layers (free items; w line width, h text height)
Top Overlay:
  text "This document can handle board shapes up to 7.9in x 10in, although" at 150,2925 h60
  text "our panel vendors top out at 7in x 10in." at 150,2800.94 h60
  text "To re-size the board shape, do the following:" at 205,2676.88 h60
  text "Select lines on M1 Board Outline and delete (easy in single layer mode...shift+s)" at 265,2552.82 h60
  text "Draw a rectangle using lines (example will be for a 4\" x 6\" board" at 265,2428.76 h60
  text "Enter Place Line mode (keyboard pl)" at 475,2304.71 h60
  text "keyboard jo to jump to origin, hit enter" at 475,2180.65 h60
  text "keyboard jl to jump to location, set x to 6000, hit enter twice" at 475,2056.59 h60
  text "keyboard jl to jump to location, set x to 6000 and y to 4000, hit enter twice" at 475,1932.53 h60
  text "keyboard jl to jump to location, set x to 0 and y to 4000, hit enter twice" at 475,1808.47 h60
  text "keyboard jo to jump to origin, hit enter" at 475,1684.41 h60
  text "Hit ESC twice to exit place line mode" at 475,1560.35 h60
  text "Select lines on M1 Board Outline" at 265,1416.3 h60
  text "Menu Design|Board Shape|Define from Selected Objects (keyboard dsd)" at 265,1312.24 h60
  text "To define a Keep-Out that mirrors the board outline:" at 150,1188.18 h60
  text "Menu Design|Board Shape|Create Primitives From Board Shape (keyboard dsp)" at 265,1064.12 h60
  text "Set the Keep-Out Layer as the layer, set width as preferred" at 475,940.06 h60
  text "Ensure Route Tool Outline is selected, hit enter" at 475,816 h60
  text "If you re-size the board, don't forget to move the drill table strings on the" at 150,493 h60
  text "Drill Drawing Layer...they should be just to the right of your board shape" at 343,387 h60
  text ".PRJ_Number" at 1690,120 h60
  text ".PCB_Rev" at 2290,120 h60
  text ".Layer_Name" at 577,-858.49 h60
Bottom Overlay:
  text ".Layer_Name" at 577,-858.49 h60
Top Paste:
  text ".Layer_Name" at 577,-858.49 h60
Bottom Paste:
  text ".Layer_Name" at 577,-858.49 h60
Top Solder:
  text ".Layer_Name" at 577,-858.49 h60
  text ".Layer_Name" at 577,-858.49 h60
Bottom Solder:
  text ".Layer_Name" at 577,-858.49 h60
Drill Guide:
  text ".Layer_Name" at 577,-858.49 h60
M1 Board Outline:
  the board outline again, w10
  text ".Layer_Name" at 577,-858.49 h60
M2 Board Dimensions:
  rectangle: 0,-275 125,-150
  rectangle: 125,-400 500,-275
  lines w7: 0,-275 1000,-275 ; 125,-400 125,-150 ; 250,-400 250,-150 ; 500,-400 500,-150 ; 750,-400 750,-150 ; 0,-400 1000,-400 1000,-150 0,-150 0,-400
  text ".Layer_Name" at 577,-858.49 h60
M3 3D STEP Top:
  text ".Layer_Name" at 577,-858.49 h60
M4 3D STEP Bottom:
  text ".Layer_Name" at 577,-858.49 h60
M5 Assembly Top:
  lines w10: -292,-930.17 6308,-930.17 ; -292,-726.83 6310,-726.83 ; -292,-523.5 -292,-1133.5 3713,-1133.5 6310,-1133.5 6310,-523.5 -291.5,-523.5 -291.5,-1133.5 1284,-1133.5 ; 2173,-1133.5 2173,-523.5 ; 3440,-726.83 3440,-523.5 ; 4280,-726.83 4280,-523.5 ; 4902,-1140 4902,-937.17
  text "COMPONENTS MARKED 'DNP' SHOULD NOT BE POPULATED." at 1153.5,-318.5 h60
  text "ASSEMBLY VARIANT:" at 1153,-434 h60
  text ".VariantName" at 2189,-434 h60
  text "PCB VIEWED FROM TOP SIDE" at -228.5,-655.67 h60
  text "BOARD #:" at 2248,-655.67 h60
  text ".PRJ_Number" at 2793.5,-655.67 h60
  text "REV:" at 3638,-655.67 h60
  text ".PCB_Rev" at 3929.5,-655.67 h60
  text "SVN REV:" at 4476,-655.67 h60
  text ".VersionControl_RevNumber" at 4982,-655.67 h60
  text "PLOT NAME =" at -228.5,-1064.34 h60
  text ".plot_File_Name" at 577,-1064.34 h60
  text "GENERATED    :" at 2250,-1064.34 h60
  text ".Print_Date" at 3119.5,-1064.34 h60
  text ".Print_Time" at 3848.5,-1064.34 h60
  text "TEXAS INSTRUMENTS" at 5113,-1064.34 h60
M6 Assembly Bottom:
  lines w10: -292.5,-727.33 6309.5,-727.33 ; -290.5,-930.67 6309.5,-930.67 ; 1115.5,-1140.5 1115.5,-937.67 ; 1737.5,-727.33 1737.5,-524 ; 2577.5,-727.33 2577.5,-524 ; 3844.5,-1134 3844.5,-524 ; 4733.5,-1134 6309,-1134 6309,-524 -292.5,-524 -292.5,-1134 2304.5,-1134 6309.5,-1134 6309.5,-524
  text "COMPONENTS MARKED 'DNP' SHOULD NOT BE POPULATED." at 6102,-318 h60
  text ".VariantName" at 5058,-434 h60
  text "ASSEMBLY VARIANT:" at 6097,-434 h60
  text ".VersionControl_RevNumber" at 1035.5,-656.17 h60
  text "SVN REV:" at 1541.5,-656.17 h60
  text ".PCB_Rev" at 2088,-656.17 h60
  text "REV:" at 2379.5,-656.17 h60
  text ".PRJ_Number" at 3224,-656.17 h60
  text "BOARD #:" at 3769.5,-656.17 h60
  text "PCB VIEWED FROM BOTTOM SIDE" at 6246,-656.17 h60
  text "TEXAS INSTRUMENTS" at 904.5,-1064.84 h60
  text ".Print_Time" at 2169,-1064.84 h60
  text ".Print_Date" at 2898,-1064.84 h60
  text "GENERATED    :" at 3767.5,-1064.84 h60
  text ".plot_File_Name" at 5440.5,-1064.84 h60
  text "PLOT NAME =" at 6246,-1064.84 h60
M9 Title Sheet:
  drawing of 57 lines, arcs and shapes, not listed
  text "1" at 739.84,8036.5 h70
  text "2" at 3235.5,8036.5 h70
  text "3" at 5724.84,8036.5 h70
  text "4" at 8231.51,8036.5 h70
  text "5" at 10730.5,8036.5 h70
  text "6" at 13235.5,8036.5 h70
  text "A" at -416.5,6893.5 h70
  text "A" at 14383.5,6893.5 h70
  text "B" at -416.5,4513.5 h70
  text "B" at 14383.5,4513.5 h70
  text "C" at -416.5,2138.5 h70
  text "C" at 14383.5,2138.5 h70
  text "PROJECT TITLE:" at 11343.5,277.5 h45
  text ".PRJ_Title" at 11393.5,144.17 h70
  text "DESIGNED FOR:" at 11343.5,-23.5 h45
  text ".PRJ_Customer" at 11393.5,-163.5 h70
  text "D" at -416.5,-231.5 h70
  text "D" at 14383.5,-231.5 h70
  text "FILE NAME:" at 11343.5,-323.5 h45
  text ".PCB_File_Name_No_Path" at 11393.5,-443.5 h70
  text "Texas Instruments (TI) and/or its licensors do not warrant the accuracy or completeness of this specification" at 6374,-605.34 h45
  text "ENGINEER:" at 11343.5,-613.5 h45
  text "LAYOUT BY:" at 12848.5,-613.5 h45
  text "or any information contained therein. TI and/or its licensors do not warrant that this design will meet" at 6329.01,-718 h45
  text ".PRJ_Engineer" at 11393.5,-768.49 h70
  text ".PCB_Layout" at 12899,-768.49 h70
  text "the specifications, will be suitable for your application or fit for any particular purpose, or will operate in" at 6329.01,-830.67 h45
  text ".Layer_Name" at 577,-858.49 h60
  text "ALTIUM DESIGNER VERSION:" at 12848.5,-923.5 h45
  text "an implementation. TI and/or its licensors do not warrant that the design is production worthy. You should" at 6329.01,-943.33 h45
  text "completely validate and test your design implementation to confirm the system functionality for your application." at 6374,-1056 h45
  text ".print_Scale" at 11393.5,-1056.83 h70
  text ".Application_BuildNumber" at 12899,-1056.83 h70
  text "1" at 739.84,-1263.5 h70
  text "2" at 3235.5,-1263.5 h70
  text "3" at 5724.84,-1263.5 h70
  text "4" at 8231.51,-1263.5 h70
  text "5" at 10730.5,-1263.5 h70
  text "6" at 13235.5,-1263.5 h70
M10 Fab Notes:
  drawing of 185 lines, arcs and shapes, not listed
  text "DESIGN INFORMATION" at 12381.02,5910 h60
  text "MIN. TRACK WIDTH:" at 11736.46,5730 h60
  text "8" at 12832.7,5730 h60
  text "MIL" at 12987.46,5730 h60
  text "MIN. CLEARANCE:" at 11736.46,5598 h60
  text "0.2" at 12772.7,5598 h60
  text "mm" at 12987.46,5598 h60
  text "MIN. VIA PAD SIZE:" at 11736.46,5466 h60
  text "24" at 12802.71,5466 h60
  text "MIL" at 12987.46,5466 h60
  text "0.05mm (2MIL)" at 12431.46,5324.29 h60
  text "MINIMUM ANNULAR RING" at 11407.23,5320 h60
  text "EXTERNAL" at 13139.46,5320 h60
  text "PER" at 11607.23,5202 h60
  text "IPC-D-275 CLASS 2 LEVEL C" at 11827.23,5202 h60
  text "MIL, HOLES" at 13315.46,5089.71 h60
  text "+/-" at 12923,5089 h60
  text "+/-" at 13777,5089 h60
  text "REGISTRATION TOLERANCES:" at 11407.23,5084 h60
  text "METAL" at 12607,5084 h60
  text "5" at 13183.2,5084 h60
  text "3" at 14016.2,5084 h60
  text "MIL" at 14132.46,5084 h60
  text "MATERIAL:" at 11332.46,4874.54 h60
  text "FR-4 High Tg" at 12318.9,4734.21 h60
  text "FR-408" at 11753.46,4725.64 h60
  text "X" at 12165.46,4725.64 h60
  text "OTHER" at 13241.46,4725.64 h60
  text "62 MIL (1.6mm) +/-10%" at 12073.56,4562.92 h60
  text "THICKNESS:" at 11407.23,4558.64 h60
  text "X" at 11945.4,4558.64 h60
  text "OTHER" at 13358.46,4558.64 h60
  text "TOLERANCE:" at 11407.23,4400.64 h60
  text "X" at 12246.53,4400.64 h60
  text "ANSI IPC-6012 TYPE 3 CLASS 2" at 12433.48,4400.64 h60
  text "OTHER +/-" at 12433.46,4244.64 h60
  text "BOW & TWIST:" at 11407.23,4087.64 h60
  text "X" at 12246.53,4087.64 h60
  text "ANSI IPC-6012 TYPE 3 CLASS 2" at 12433.48,4087.64 h60
  text "OTHER +/-" at 12433.46,3929.13 h60
  text "DRILLING:" at 11332.46,3790.64 h60
  text "REFERENCE:" at 11407.23,3673.64 h60
  text "X" at 12055.46,3673.64 h60
  text "AS SHOWN" at 12242.46,3673.64 h60
  text "X" at 12956.46,3673.64 h60
  text "NC_DRILL FILES" at 13093.46,3673.64 h60
  text "PTH MIN COPPER THICKNESS:" at 11407.23,3515.64 h60
  text "X" at 12757.46,3515.64 h60
  text "1MIL" at 12894.46,3515.64 h60
  text "OTHER" at 13391.46,3515.64 h60
  text "BOARD FINISH:" at 11332.46,3356.64 h60
  text "SILKSCREEN:" at 11487.68,3238.64 h60
  text "X" at 12436.46,3238.64 h60
  text "TOP" at 12562.46,3238.64 h60
  text "X" at 12946.46,3238.64 h60
  text "BOTTOM" at 13073.46,3238.64 h60
  text "SILKSCREEN COLOR:" at 11487.68,3071.64 h60
  text "X" at 12435.42,3071.64 h60
  text "WHITE" at 12562.46,3071.64 h60
  text "OTHER" at 13073.46,3071.64 h60
  text "SOLDER RESIST COLOR:" at 11487.68,2901.64 h60
  text "X" at 12055.42,2742.44 h60
  text "GREEN" at 12182.46,2742.44 h60
  text "BLUE" at 12773.46,2742.44 h60
  text "OTHER" at 13311.46,2742.44 h60
  text "IMMERSION GOLD (ENIG)" at 12393.46,2553.92 h60
  text "ENEPIG" at 13731,2550.64 h60
  text "SURFACE FINISH:" at 11332.46,2549.64 h60
  text "X" at 12206.51,2549.64 h60
  text "IMM. TIN/SILVER OR EQUIV" at 11662,2392.64 h60
  text "OTHER" at 13093.46,2392.64 h60
  text "ARRAY/PANEL:" at 11332.46,2213.64 h60
  text "CUT AND TRIM PER MECH LAYER 1" at 12393.46,2209.35 h60
  text "N.C. ROUTE" at 12393.46,2057.64 h60
  text "X" at 13072.46,2057.64 h60
  text "V. SCORE" at 13259.46,2057.64 h60
  text "CERTIFICATION:" at 11332.46,1920.64 h60
  text "MATERIALS AND WORKMANSHIP FOR ALL PCBS" at 12057.46,1920.64 h60
  text "TO MEET OR EXCEED THE REQUIREMENTS OF:" at 12057.46,1822.64 h60
  text "X" at 11683.96,1686.13 h60
  text "ANSI IPC-A-600F CLASS ->" at 11822.96,1686.13 h60
  text "X" at 13462.02,1686.13 h60
  text "2" at 13580.96,1686.14 h60
  text "1" at 13265.96,1684.64 h60
  text "3" at 13934.96,1684.64 h60
  text "X" at 11686.02,1526.64 h60
  text "UL 94V-0" at 11822.96,1526.64 h60
  text "X" at 12498.02,1526.64 h60
  text "RoHS" at 12634.96,1526.64 h60
  text "OTHER" at 13279.36,1526.64 h60
  text "PER ORDER" at 13676.42,1526.64 h60
  text "ADDITIONAL REQUIREMENTS:" at 11332.46,1385.64 h60
  text "MICROSECTION:" at 11407.23,1270.64 h60
  text "YES" at 12312.96,1270.64 h60
  text "REQUIRED" at 13174.46,1114.49 h60
  text "BARE BOARD ELEC. TEST:" at 11407.23,1111.64 h60
  text "NONE" at 12712.96,1111.64 h60
  text "X" at 13047.46,1111.64 h60
  text "PER ORDER" at 13766.46,1111.64 h60
  text "MANUFACTURER'S UL:" at 11407.23,954.64 h60
  text "RAIL" at 12572.96,950.35 h60
  text "METAL" at 13064.77,950.35 h60
  text "X" at 13440,950 h60
  text "SILK" at 13576.46,950.35 h60
  text ".Layer_Name" at 577,-858.49 h60
M11 Gerber Information:
  lines w10: -292,-930.17 6308,-930.17 ; -292,-726.83 6310,-726.83 ; -292,-523.5 -292,-1133.5 3713,-1133.5 6310,-1133.5 6310,-523.5 -291.5,-523.5 -291.5,-1133.5 1284,-1133.5 ; 2173,-1133.5 2173,-523.5 ; 3440,-726.83 3440,-523.5 ; 4280,-726.83 4280,-523.5 ; 4902,-1140 4902,-937.17
  text "ALL ARTWORK VIEWED FROM TOP SIDE" at -228.5,-655.67 h60
  text "BOARD #:" at 2248,-655.67 h60
  text ".PRJ_Number" at 2793.5,-655.67 h60
  text "REV:" at 3638,-655.67 h60
  text ".PCB_Rev" at 3929.5,-655.67 h60
  text "SVN REV:" at 4476,-655.67 h60
  text ".VersionControl_RevNumber" at 4982,-655.67 h60
  text "LAYER NAME =" at -228.5,-858.49 h60
  text "PLOT NAME =" at -228.5,-1064.34 h60
  text ".plot_File_Name" at 577,-1064.34 h60
  text "GENERATED    :" at 2250,-1064.34 h60
  text ".Print_Date" at 3119.5,-1064.34 h60
  text ".Print_Time" at 3848.5,-1064.34 h60
  text "TEXAS INSTRUMENTS" at 5113,-1064.34 h60
M12 Stackup:
  drawing of 191 lines, arcs and shapes, not listed
  text "Layer" at 9790.58,7830 h60
  text "Name" at 10200.49,7830 h60
  text "Material" at 11130.23,7830 h60
  text "Thickness" at 11990,7830 h60
  text "Constant" at 12639.84,7830 h60
  text "Board Layer Stack" at 13209.7,7830 h60
  text "1" at 9790.58,7710 h60
  text "Top Overlay" at 10200.49,7710 h60
  text "2" at 9790.58,7590 h60
  text "Top Solder" at 10200.49,7590 h60
  text "Solder Resist" at 11130.23,7590 h60
  text "0.40mil" at 11990,7590 h60
  text "3.5" at 12639.84,7590 h60
  text "3" at 9790.58,7470 h60
  text "Top Layer" at 10200.49,7470 h60
  text "Copper" at 11130.23,7470 h60
  text "1.40mil" at 11990,7470 h60
  text "4" at 9790.58,7350 h60
  text "Dielectric1" at 10200.49,7350 h60
  text "FR-4" at 11130.23,7350 h60
  text "59.20mil" at 11990,7350 h60
  text "4.8" at 12639.84,7350 h60
  text "5" at 9790.58,7230 h60
  text "Bottom Layer" at 10200.49,7230 h60
  text "Copper" at 11130.23,7230 h60
  text "1.40mil" at 11990,7230 h60
  text "6" at 9790.58,7110 h60
  text "Bottom Solder" at 10200.49,7110 h60
  text "Solder Resist" at 11130.23,7110 h60
  text "0.40mil" at 11990,7110 h60
  text "3.5" at 12639.84,7110 h60
  text "7" at 9790.58,6990 h60
  text "Bottom Overlay" at 10200.49,6990 h60
  text ".Layer_Name" at 577,-858.49 h60
M13 Component Bodies Top:
  text ".Layer_Name" at 577,-858.49 h60
M14 Component Bodies Bottom:
  text ".Layer_Name" at 577,-858.49 h60
M15 Courtyards Top:
  text ".Layer_Name" at 577,-858.49 h60
M16 Courtyards Bottom:
  text ".Layer_Name" at 577,-858.49 h60
Drill Drawing:
  circle w1: c5572.72,3221.04 r24.89
  lines w1: 5547.83,2947.29 5597.6,2947.29 5572.72,2897.52 5547.83,2947.29 ; 5547.83,3059.28 5560.27,3059.28 5572.72,3046.84 5585.16,3059.28 5597.6,3059.28 5585.16,3071.72 5597.6,3084.17 5585.16,3084.17 5572.72,3096.61 5560.27,3084.17 5547.83,3084.17 5560.27,3071.72 5547.83,3059.28
  lines w12: 5480,2852.72 7598.02,2852.72 ; 5480,3300.68 7598.02,3300.68 ; 5850.36,2703.4 5850.36,3450 ; 6207.36,2703.4 6207.36,3450 ; 6868.93,2703.4 6868.93,3450 ; 7153.07,2703.4 7153.07,3450 ; 5480,2703.4 7598.02,2703.4 7598.02,3450 5480,3450 5480,2703.4
  text "Symbol" at 5569.59,3345.48 h72
  text "Quantity" at 5895.16,3345.48 h72
  text "Finished Hole Size" at 6252.16,3345.48 h72
  text "Plated" at 6913.72,3345.48 h72
  text "Hole Type" at 7197.86,3345.48 h72
  text "20" at 5895.16,3196.16 h60
  text "7.87mil (0.200mm)" at 6252.16,3196.16 h60
  text "PTH" at 6913.72,3196.16 h60
  text "Round" at 7197.86,3196.16 h60
  text "2" at 5895.16,3046.84 h60
  text "40.00mil (1.016mm)" at 6252.16,3046.84 h60
  text "PTH" at 6913.72,3046.84 h60
  text "Round" at 7197.86,3046.84 h60
  text "18" at 5895.16,2897.52 h60
  text "50.00mil (1.270mm)" at 6252.16,2897.52 h60
  text "PTH" at 6913.72,2897.52 h60
  text "Round" at 7197.86,2897.52 h60
  text "40 Total" at 5895.16,2748.2 h60
  text ".Layer_Name" at 577,-858.49 h60

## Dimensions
0,-400 to 1000,-400 on M2 Board Dimensions
0,0 to 0,3450 on M2 Board Dimensions
0,0 to 4950,0 on M2 Board Dimensions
